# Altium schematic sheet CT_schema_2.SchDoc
size 283 x 135 mm
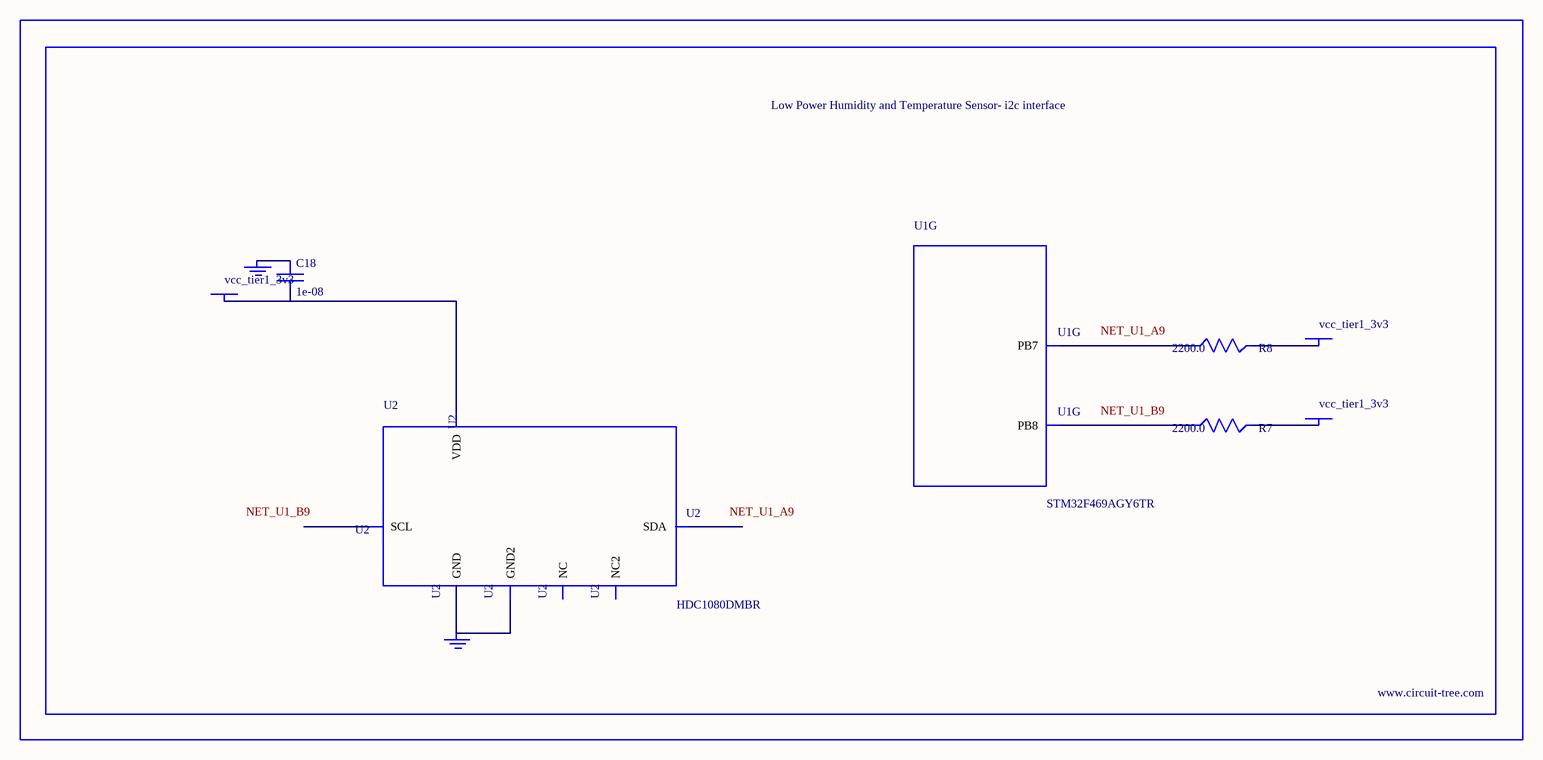
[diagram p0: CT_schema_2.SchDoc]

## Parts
BORDER1  (no value)
C18  1e-08  [C0402]
GND_INSTANCE_1_0  (no value)
GND_INSTANCE_1_1  (no value)
POWER_INSTANCE_1_0  vcc_tier1_3v3
POWER_INSTANCE_1_1  vcc_tier1_3v3
POWER_INSTANCE_1_2  vcc_tier1_3v3
R7  2200.0  [R0603]
R8  2200.0  [R0603]
U1  STM32F469AGY6TR  [WLCSP168]  (part G of 13)
U2  HDC1080DMBR  [WSON-6]

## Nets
NetC18_1: C18.1 GND_INSTANCE_1_0.0(GND)
NetC18_2: C18.2 POWER_INSTANCE_1_0.0(PWR) U2.5(VDD)
NetGND_INSTANCE_1_1_0: GND_INSTANCE_1_1.0(GND) U2.2(GND) U2.PAD(GND2)
NetPOWER_INSTANCE_1_1_0: POWER_INSTANCE_1_1.0(PWR) R8.2
NetPOWER_INSTANCE_1_2_0: POWER_INSTANCE_1_2.0(PWR) R7.2
NetR7_1: R7.1 U1.B9(PB8)
NetR8_1: R8.1 U1.A9(PB7)

Not connected (* = marked no-connect by the designer): U2 1(SDA) 3(NC) 4(NC2) 6(SCL)

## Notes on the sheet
- Labels drawn without touching a wire or pin: NET_U1_A9, NET_U1_B9

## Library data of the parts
BORDER1 = BORDER_PAGE1
C18 = C0402C103K3RAC
GND_INSTANCE_1_0 GND_INSTANCE_1_1 = GND
POWER_INSTANCE_1_0-POWER_INSTANCE_1_2 = PWR
R7 R8 = RC0603JR-072K2L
